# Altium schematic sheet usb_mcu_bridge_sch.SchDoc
size 431 x 279 mm; Date: Not shown in title block; ApprovedBy: Not shown in title block; CheckedBy: Not shown in title block; Author: Not shown in title block; CompanyName: Not shown in title block; Engineer: Not shown in title block; Organization: Not shown in title block; Address1: Not shown in title block; Address2: Not shown in title block; Address3: Not shown in title block; Address4: Not shown in title block; DocumentNumber: 2; Revision: Use project parameter SCH_Rev; SheetNumber: 2; SheetTotal: 4; PageSetup: Record=PageOptions|CenterHorizontal=True|CenterVertical=True|PrintScale=0.62|XCorrection=1.00|YCorrection=1.00|PrintKind=0|BorderSize=5000000|LeftOffset=0|BottomOffset=0|Orientation=2|PaperLength=1000|PaperWidth=1000|Scale=100|PaperSource=15|PrintQuality=600|MediaType=1|DitherType=10|PaperKind=Letter|PrintScaleMode=1
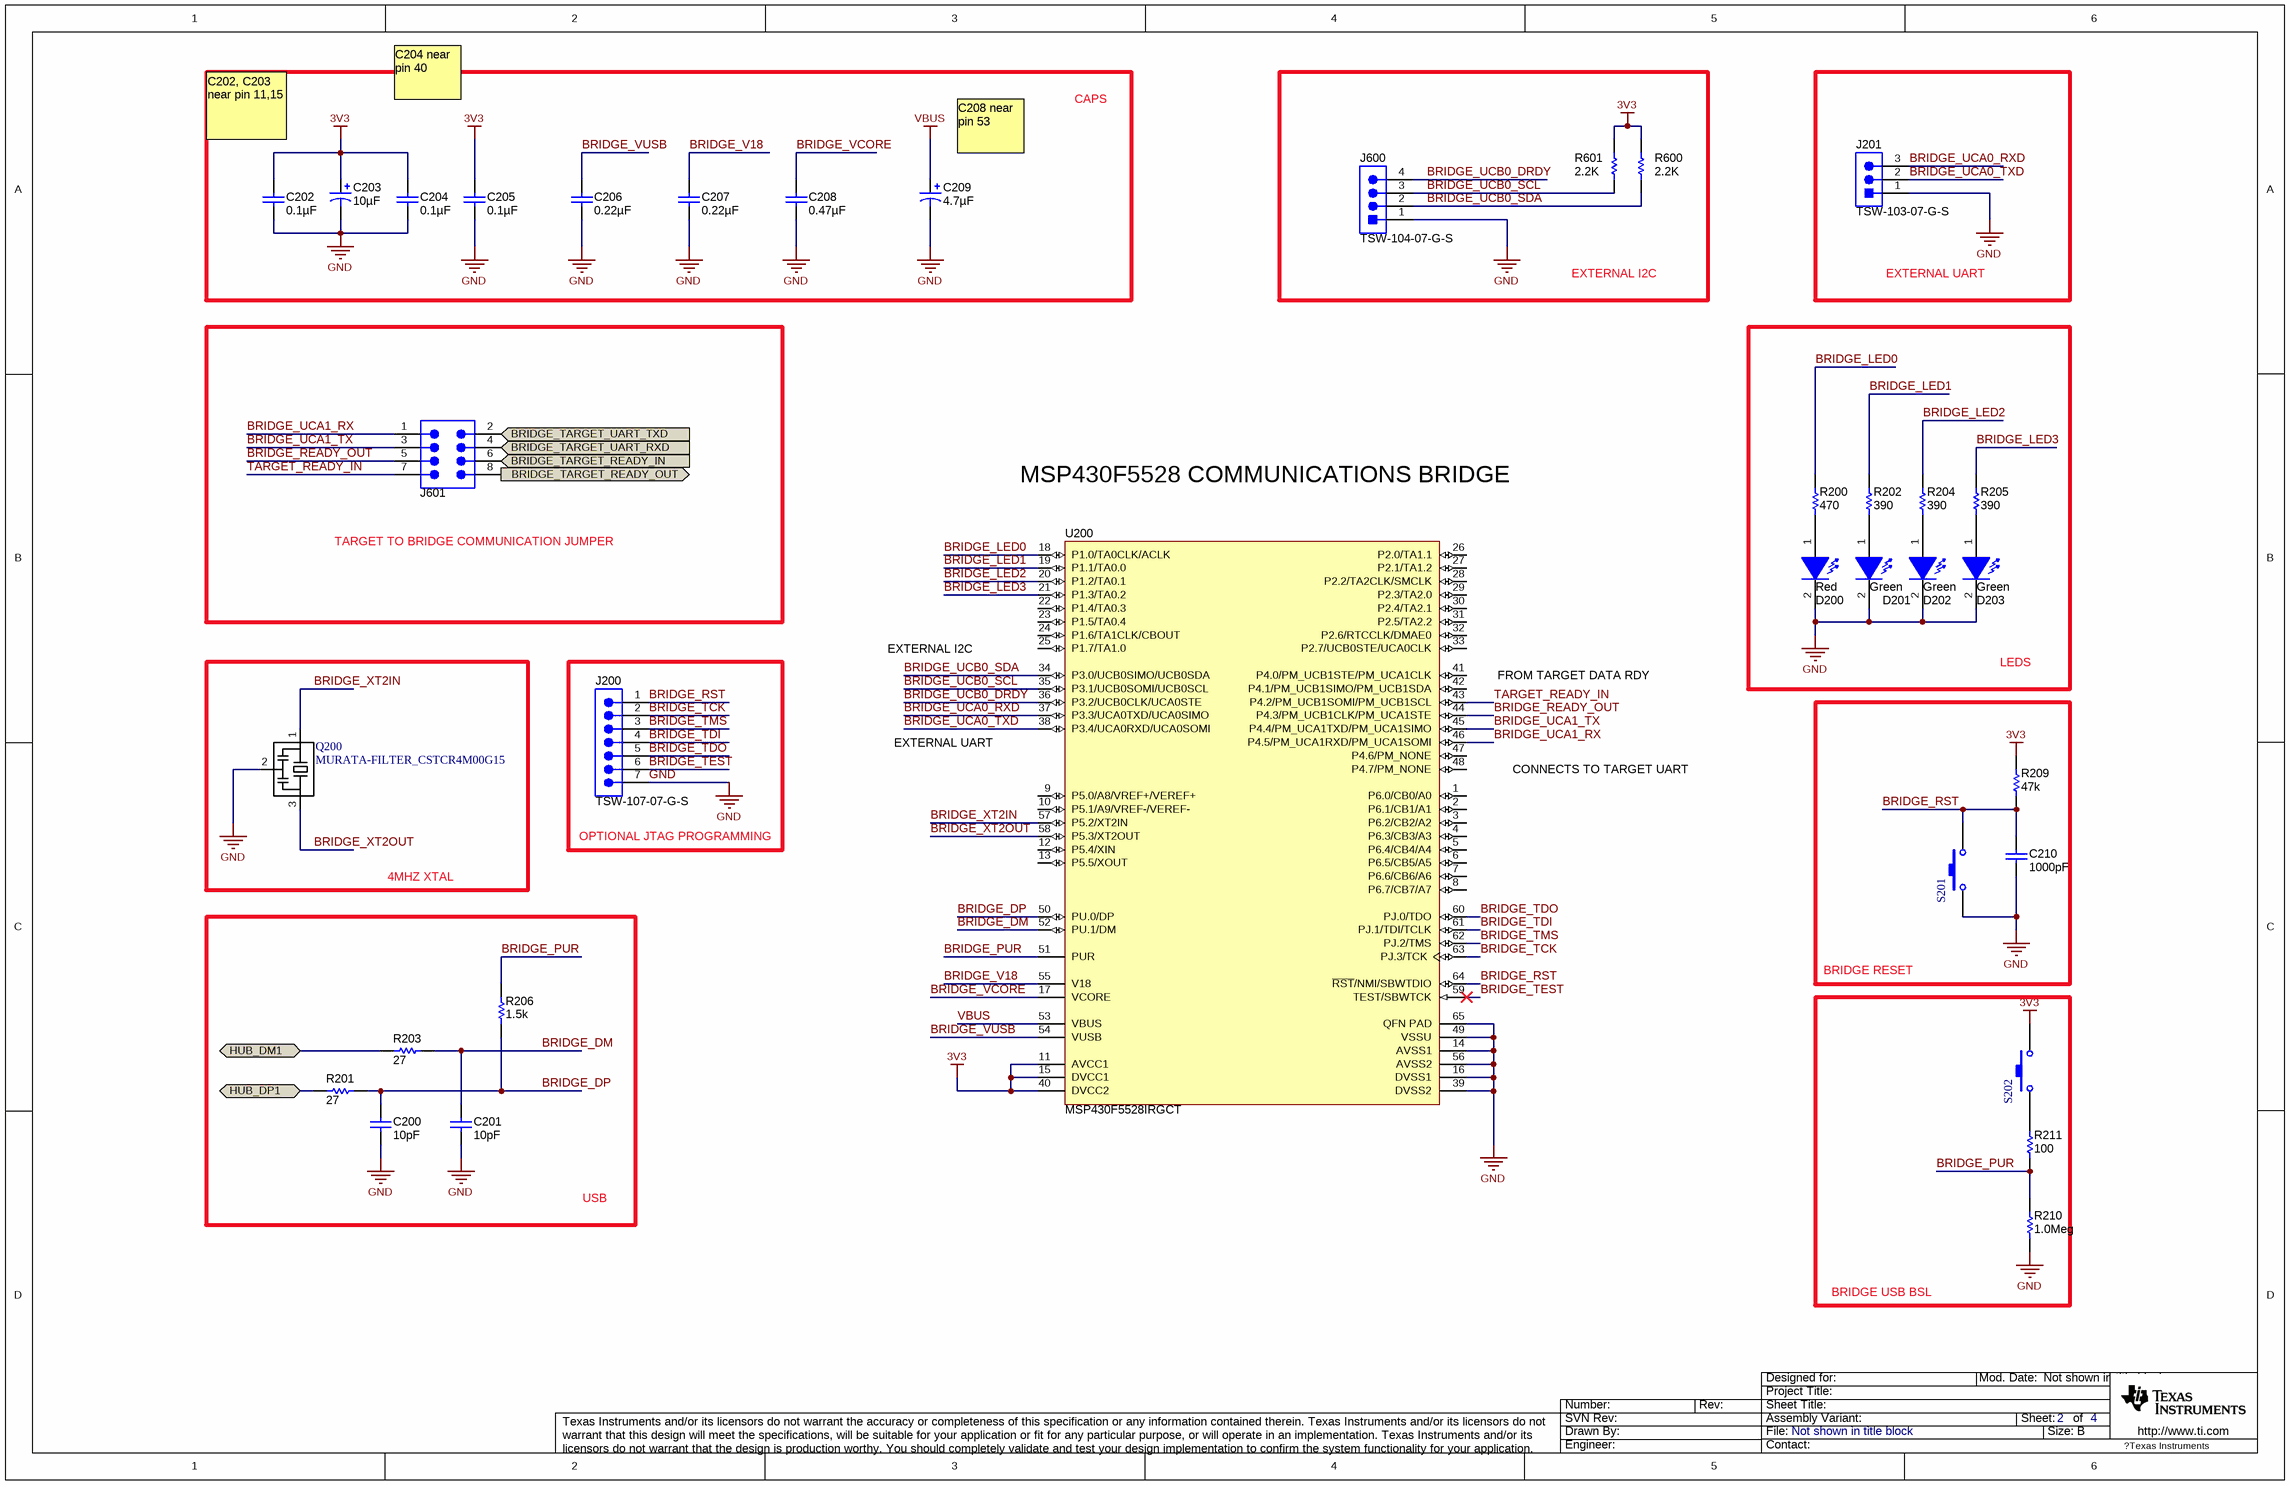
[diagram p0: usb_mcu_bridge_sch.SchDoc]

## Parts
C200  ValueDisplayed: 10pF  [0402]  (hidden comment: GRM1555C1H100JA01D)
C201  ValueDisplayed: 10pF  [0402]  (hidden comment: GRM1555C1H100JA01D)
C202  ValueDisplayed: 0.1µF  [0402]  (hidden comment: GRM155R61C104KA88D)
C203  ValueDisplayed: 10µF  [3216-18]  (hidden comment: TPSA106M010R1800)
C204  ValueDisplayed: 0.1µF  [0402]  (hidden comment: GRM155R61C104KA88D)
C205  ValueDisplayed: 0.1µF  [0402]  (hidden comment: GRM155R61C104KA88D)
C206  ValueDisplayed: 0.22µF  [0402]  (hidden comment: GRM155R61A224KE19D)
C207  ValueDisplayed: 0.22µF  [0402]  (hidden comment: GRM155R61A224KE19D)
C208  ValueDisplayed: 0.47µF  [0402]  (hidden comment: GRM155R61A474KE15D)
C209  ValueDisplayed: 4.7µF  [3216-18]  (hidden comment: 293D106X0010A2TE3)
C210  ValueDisplayed: 1000pF  [0402]  (hidden comment: C1005X7R1H102K)
D200  value Red  [LED_LTST-C190_Red]  (hidden comment: LTST-C190CKT)
D201  value Green  [LED_LTST-C190]  (hidden comment: LTST-C190GKT)
D202  value Green  [LED_LTST-C190]  (hidden comment: LTST-C190GKT)
D203  value Green  [LED_LTST-C190]  (hidden comment: LTST-C190GKT)
J200  TSW-107-07-G-S  [TSW-107-07-G-S]
J201  TSW-103-07-G-S  [TSW-103-07-G-S]
J600  TSW-104-07-G-S  [TSW-104-07-G-S]
J601  TSW-104-07-G-D  [TSW-104-07-G-D]  (value not drawn)
Q200  MURATA-FILTER_CSTCR4M00G15  [CSTCR CERAMIC RESONATOR - MURATA]
R200  value 470  [0402]  (hidden comment: CRCW0402470RJNED)
R201  value 27  [0402]  (hidden comment: CRCW040227R0JNED)
R202  value 390  [0402]  (hidden comment: CRCW0402390RJNED)
R203  value 27  [0402]  (hidden comment: CRCW040227R0JNED)
R204  value 390  [0402]  (hidden comment: CRCW0402390RJNED)
R205  value 390  [0402]  (hidden comment: CRCW0402390RJNED)
R206  value 1.5k  [0402]  (hidden comment: CRCW04021K40FKED)
R209  value 47k  [0402]  (hidden comment: CRCW040247K0JNED)
R210  value 1.0Meg  [0402]  (hidden comment: CRCW04021M00JNED)
R211  value 100  [0402]  (hidden comment: CRCW0402100RJNED)
R600  value 2.2K  [0402]  (hidden comment: CRCW04024K70JNED)
R601  value 2.2K  [0402]  (hidden comment: CRCW04024K70JNED)
S201  (no value)  [B3U-1000P]
S202  (no value)  [B3U-1000P]
U200  MSP430F5528IRGCT  [TI_RGC0064B_N]

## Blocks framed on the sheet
CAPS: C202-C209
EXTERNAL I2C: J600 R600 R601
EXTERNAL UART: J201
TARGET TO BRIDGE COMMUNICATION JUMPER: J601
LEDS: D200-D203 R200 R202 R204 R205
4MHZ XTAL: Q200
OPTIONAL JTAG PROGRAMMING: J200
BRIDGE RESET: C210 R209 S201
USB: C200 C201 R201 R203 R206
BRIDGE USB BSL: R210 R211 S202

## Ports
BRIDGE_TARGET_READY_IN (out), BRIDGE_TARGET_READY_OUT (in), BRIDGE_TARGET_UART_RXD (out), BRIDGE_TARGET_UART_TXD (in), HUB_DM1 (bidir), HUB_DP1 (bidir)

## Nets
3V3: C202.1 C203.1(+) C204.1 C205.1 R209.2 R600.1 R601.1 S202.2 U200.11(AVCC1) U200.15(DVCC1) U200.40(DVCC2)
GND: C200.2 C201.2 C202.2 C203.2(-) C204.2 C205.2 C206.2 C207.2 C208.2 C209.2(-) C210.2 D200.2(K) D201.2(K) D202.2(K) D203.2(K) J200.7 J201.1 J600.1 Q200.2 R210.1 S201.1 U200.14(AVSS1) U200.16(DVSS1) U200.39(DVSS2) U200.49(VSSU) U200.56(AVSS2) U200.65(QFN_PAD)
VBUS: C209.1(+) U200.53(VBUS)
BRIDGE_DM: C201.1 R203.2 U200.52(PU.1/DM)
BRIDGE_DP: C200.1 R201.2 R206.1 U200.50(PU.0/DP)
BRIDGE_LED0: R200.2 U200.18(P1.0/TA0CLK/ACLK)
BRIDGE_LED1: R202.2 U200.19(P1.1/TA0.0)
BRIDGE_LED2: R204.2 U200.20(P1.2/TA0.1)
BRIDGE_LED3: R205.2 U200.21(P1.3/TA0.2)
BRIDGE_PUR: R206.2 R210.2 R211.1 U200.51(PUR)
BRIDGE_READY_OUT: J601.5 U200.44(P4.3/PM_UCB1CLK/PM_UCA1STE)
BRIDGE_RST: C210.1 J200.1 R209.1 S201.2 U200.64(~{RST}/NMI/SBWTDIO)
BRIDGE_TARGET_READY_IN: J601.6 ; port BRIDGE_TARGET_READY_IN
BRIDGE_TARGET_READY_OUT: J601.8 ; port BRIDGE_TARGET_READY_OUT
BRIDGE_TARGET_UART_RXD: J601.4 ; port BRIDGE_TARGET_UART_RXD
BRIDGE_TARGET_UART_TXD: J601.2 ; port BRIDGE_TARGET_UART_TXD
BRIDGE_TCK: J200.2 U200.63(PJ.3/TCK)
BRIDGE_TDI: J200.4 U200.61(PJ.1/TDI/TCLK)
BRIDGE_TDO: J200.5 U200.60(PJ.0/TDO)
BRIDGE_TEST: J200.6 U200.59(TEST/SBWTCK)
BRIDGE_TMS: J200.3 U200.62(PJ.2/TMS)
BRIDGE_UCA0_RXD: J201.3 U200.37(P3.3/UCA0TXD/UCA0SIMO)
BRIDGE_UCA0_TXD: J201.2 U200.38(P3.4/UCA0RXD/UCA0SOMI)
BRIDGE_UCA1_RX: J601.1 U200.46(P4.5/PM_UCA1RXD/PM_UCA1SOMI)
BRIDGE_UCA1_TX: J601.3 U200.45(P4.4/PM_UCA1TXD/PM_UCA1SIMO)
BRIDGE_UCB0_DRDY: J600.4 U200.36(P3.2/UCB0CLK/UCA0STE)
BRIDGE_UCB0_SCL: J600.3 R601.2 U200.35(P3.1/UCB0SOMI/UCB0SCL)
BRIDGE_UCB0_SDA: J600.2 R600.2 U200.34(P3.0/UCB0SIMO/UCB0SDA)
BRIDGE_V18: C207.1 U200.55(V18)
BRIDGE_VCORE: C208.1 U200.17(VCORE)
BRIDGE_VUSB: C206.1 U200.54(VUSB)
BRIDGE_XT2IN: Q200.1 U200.57(P5.2/XT2IN)
BRIDGE_XT2OUT: Q200.3 U200.58(P5.3/XT2OUT)
HUB_DM1: R203.1 ; port HUB_DM1
HUB_DP1: R201.1 ; port HUB_DP1
TARGET_READY_IN: J601.7 U200.43(P4.2/PM_UCB1SOMI/PM_UCB1SCL)
NetD200_1: D200.1(A) R200.1
NetD201_1: D201.1(A) R202.1
NetD202_1: D202.1(A) R204.1
NetD203_1: D203.1(A) R205.1
NetR211_2: R211.2 S202.1

Not connected (* = marked no-connect by the designer): U200 1(P6.0/CB0/A0) 2(P6.1/CB1/A1) 3(P6.2/CB2/A2) 4(P6.3/CB3/A3) 5(P6.4/CB4/A4) 6(P6.5/CB5/A5) 7(P6.6/CB6/A6) 8(P6.7/CB7/A7) 9(P5.0/A8/VREF+/VEREF+) 10(P5.1/A9/VREF-/VEREF-) 12(P5.4/XIN) 13(P5.5/XOUT) 22(P1.4/TA0.3) 23(P1.5/TA0.4) 24(P1.6/TA1CLK/CBOUT) 25(P1.7/TA1.0) 26(P2.0/TA1.1) 27(P2.1/TA1.2) 28(P2.2/TA2CLK/SMCLK) 29(P2.3/TA2.0) 30(P2.4/TA2.1) 31(P2.5/TA2.2) 32(P2.6/RTCCLK/DMAE0) 33(P2.7/UCB0STE/UCA0CLK) 41(P4.0/PM_UCB1STE/PM_UCA1CLK) 42(P4.1/PM_UCB1SIMO/PM_UCB1SDA) 47(P4.6/PM_NONE) 48(P4.7/PM_NONE)

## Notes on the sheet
- C204 near pin 40
- C202, C203 near pin 11,15
- (near C209) C208 near pin 53
- MSP430F5528 COMMUNICATIONS BRIDGE
- EXTERNAL I2C
- FROM TARGET DATA RDY
- EXTERNAL UART
- CONNECTS TO TARGET UART

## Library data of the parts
C200 C201 = GRM1555C1H100JA01D: CAP, CERM, 10pF, 50V, +/-5%, C0G/NP0, 0402; Manufacturer: MuRata; Polarized: N; CompType: Capacitor; U/M: EA; Cap_F: 0.00000000001; Tolerance_%: 5; Value1: Unknown; VDC_V: 50; TaMin_C: -55; TaMax_C: 125
C202 C204 C205 = GRM155R61C104KA88D: CAP, CERM, 0.1uF, 16V, +/-10%, X5R, 0402; Manufacturer: MuRata; Polarized: N; CompType: Capacitor; U/M: EA; Cap_F: 0.0000001; Tolerance_%: 10; Value1: Unknown; VDC_V: 16; TaMin_C: -55; TaMax_C: 85
C203 = TPSA106M010R1800: CAP, TA, 10uF, 10V, +/-20%, 1.8 ohm, SMD; Manufacturer: AVX; Polarized: Y; CompType: Capacitor; U/M: EA; Cap_F: 0.00001; Tolerance_%: 20; Value1: 1.8 ohm; VDC_V: 10; ESR_Ohm: 1.8; IRMS_A: 0.184; TaMin_C: -55; TaMax_C: 125; Cap_Case: A
C206 C207 = GRM155R61A224KE19D: CAP, CERM, 0.22uF, 10V, +/-10%, X5R, 0402; Manufacturer: MuRata; Polarized: N; CompType: Capacitor; U/M: EA; Cap_F: 0.00000022; Tolerance_%: 10; Value1: Unknown; TaMin_C: -55; TaMax_C: 85
C208 = GRM155R61A474KE15D: CAP, CERM, 0.47uF, 10V, +/-10%, X5R, 0402; Manufacturer: MuRata; Polarized: N; CompType: Capacitor; U/M: EA; Cap_F: 0.00000047; Tolerance_%: 10; Value1: Unknown; TaMin_C: -55; TaMax_C: 85
C209 = 293D106X0010A2TE3: CAP, TA, 10uF, 10V, +/-20%, 3.4 ohm, SMD; Manufacturer: TPSA475K010R1400; Polarized: Y; CompType: Capacitor; U/M: EA; Cap_F: 0.00001; Tolerance_%: 20; Value1: 3.4 ohm; VDC_V: 10; ESR_Ohm: 3.4; IRMS_A: 0.15; TaMin_C: -55; TaMax_C: 125; Cap_Case: A
C210 = C1005X7R1H102K: CAP, CERM, 1000pF, 50V, +/-10%, X7R, 0402; Manufacturer: TDK; Polarized: N; CompType: Capacitor; U/M: EA; Cap_F: 0.000000001; Tolerance_%: 10; ESR_Ohm: 0.2381; Value1: 0.2381 ohm; VDC_V: 50; TaMin_C: -55; TaMax_C: 125
D200 = LTST-C190CKT: LED, Red, SMD; Manufacturer: Lite-On; Vf_V: 2; Value2: 2V; Io_A: 0.02; Tjmax_C: 85; Power_TotalModule: 0.0625; Value1: 0.0625W; U/M: EA
D201-D203 = LTST-C190GKT: LED, Green, SMD; Manufacturer: Lite-On; Vf_V: 2.1; Value2: 2.1V; Io_A: 0.02; Power_TotalModule: 0.1; Value1: 0.1W; U/M: EA
J200 = TSW-107-07-G-S: Header, TH, 100mil, 7x1, Gold plated, (modified silk pin #1); Manufacturer: Samtec; U/M: EA
J201 = TSW-103-07-G-S: Header, TH, 100mil, 3x1, Gold plated, 230 mil above insulator; Manufacturer: Samtec; SymbolCreator: a0799628; U/M: EA
J600 = TSW-104-07-G-S: Header, TH, 100mil, 4x1, Gold plated, 230 mil above insulator; Manufacturer: Samtec; SymbolCreator: a0412235; U/M: EA
J601 = TSW-104-07-G-D: Header, TH, 100mil, 4x2, Gold plated, 230 mil above insulator; Manufacturer: Samtec; U/M: EA
Q200 = MURATA-FILTER_CSTCR4M00G15: Value Displayed: 4.00MHz
R200 = CRCW0402470RJNED: RES, 470 ohm, 5%, 0.063W, 0402; Manufacturer: Vishay-Dale; CompType: Resistor; Value_Code: 470R; Tolerance_%: 5; Power_W: 0.063; VDC_V: 50; TempCo: 200 ppm/C; EIA_Code: E24; U/M: EA
R201 R203 = CRCW040227R0JNED: RES, 27 ohm, 5%, 0.063W, 0402; Manufacturer: Vishay-Dale; CompType: Resistor; Value_Code: 27R0; Tolerance_%: 5; Power_W: 0.063; VDC_V: 50; TempCo: 200 ppm/C; EIA_Code: E24; U/M: EA
R202 R204 R205 = CRCW0402390RJNED: RES, 390 ohm, 5%, 0.063W, 0402; Manufacturer: Vishay-Dale; CompType: Resistor; Value_Code: 390R; Tolerance_%: 5; Power_W: 0.063; VDC_V: 50; TempCo: 200 ppm/C; EIA_Code: E24; U/M: EA
R206 = CRCW04021K40FKED: RES, 1.40k ohm, 1%, 0.063W, 0402; Manufacturer: Vishay-Dale; CompType: Resistor; Res_ohm: 1400; Value_Code: 1k40; Tolerance_%: 1; Power_W: 0.063; VDC_V: 50; TempCo: 100 ppm/C; EIA_Code: E96; U/M: EA
R209 = CRCW040247K0JNED: RES, 47k ohm, 5%, 0.063W, 0402; Manufacturer: Vishay-Dale; CompType: Resistor; Res_ohm: 47000; Value_Code: 47k0; Tolerance_%: 5; Power_W: 0.063; VDC_V: 50; TempCo: 200 ppm/C; EIA_Code: E24; U/M: EA
R210 = CRCW04021M00JNED: RES, 1.0Meg ohm, 5%, 0.063W, 0402; Manufacturer: Vishay-Dale; CompType: Resistor; Res_ohm: 1000000; Value_Code: 1M00; Tolerance_%: 5; Power_W: 0.063; VDC_V: 50; TempCo: 200 ppm/C; EIA_Code: E24; U/M: EA
R211 = CRCW0402100RJNED: RES, 100 ohm, 5%, 0.063W, 0402; Manufacturer: Vishay-Dale; CompType: Resistor; Value_Code: 100R; Tolerance_%: 5; Power_W: 0.063; VDC_V: 50; TempCo: 200 ppm/C; EIA_Code: E24; U/M: EA
R600 R601 = CRCW04024K70JNED: RES, 4.7k ohm, 5%, 0.063W, 0402; Manufacturer: Vishay-Dale; CompType: Resistor; Res_ohm: 4700; Value_Code: 4k70; Tolerance_%: 5; Power_W: 0.063; VDC_V: 50; TempCo: 200 ppm/C; EIA_Code: E24; U/M: EA
S201 S202 = SW-PB: Switch
U200 = MSP430F5528IRGCT: 25 MHz Mixed Signal Microcontroller with 128 KB Flash, 8192 B SRAM and 47 GPIOs, -40 to 85 degC, 64-pin QFN (RGC), Green (RoHS & no Sb/Br); Manufacturer: Texas Instruments; ADC: 12-bit SAR; ADC Channels: 16; Brown Out Reset: Yes; DMA: 3; Flash(KB): 128; Frequency(MHz): 25; GPIO: 47; Multiplier: 32x32; SRAM(B): 8192; SubFamily: 5 Series; Timers - 16-bit: 4; USB: 1; USCI_A (UART/LIN/IrDA/SPI): 2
